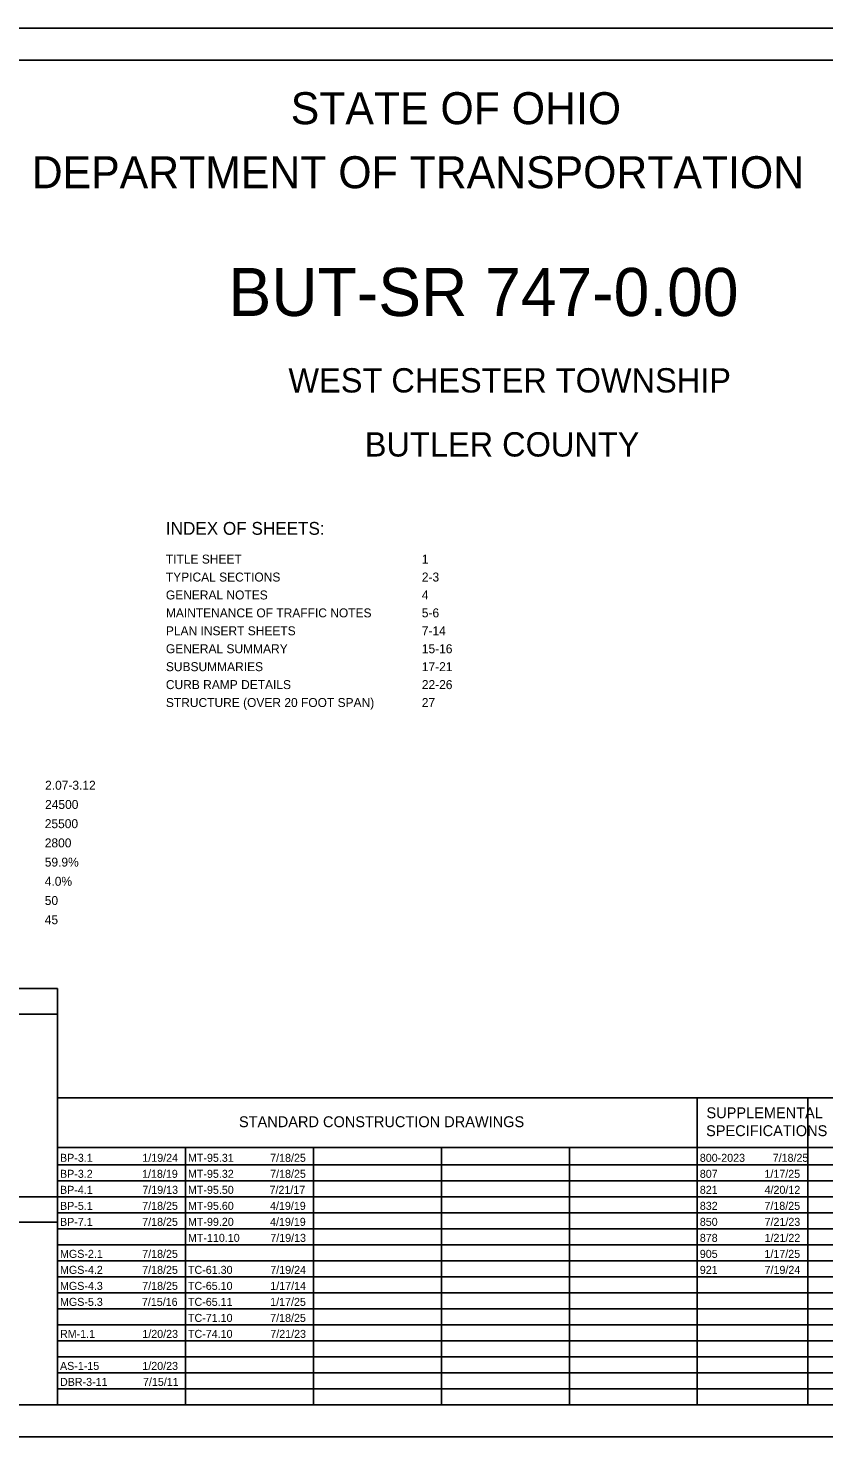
# Model space of a CAD drawing. Extents: x 0 to 34, y 0 to 22.
# Drawn here: x 9.69 to 22.13, y 0 to 22 of the extents above; entities that cross this region are included whole.
import ezdxf

# ---------------------------------------------------------------- set-up
doc = ezdxf.new("R2010")
doc.units = 0
for name, color, linetype in [('SH_Border', 7, 'Continuous'), ('SH_Cut_Line', 7, 'Continuous'), ('SH_Data', 7, 'Continuous'), ('SH_Text', 7, 'Continuous')]:
    doc.layers.add(name, color=color, linetype=linetype)

msp = doc.modelspace()

# ---------------------------------------------------------------- linework, layer by layer
at = {"layer": 'SH_Border'}
msp.add_lwpolyline([(1.5, 21.5), (33.5, 21.5), (33.5, 0.5), (1.5, 0.5)], close=True, dxfattribs=at)
at = {"layer": 'SH_Cut_Line'}
msp.add_lwpolyline([(0, 0), (34, 0), (34, 22), (0, 22)], close=True, dxfattribs=at)
at = {"layer": 'SH_Data'}
for p, q in [((7.35, 6.6), (10.15, 6.6)), ((10.15, 5.292), (23.6, 5.292)), ((10.15, 0.5), (10.15, 5.292)), ((20.15, 0.5), (20.15, 5.292)), ((21.875, 0.5), (21.875, 5.292)), ((10.15, 4.521), (23.6, 4.521)), ((12.15, 0.5), (12.15, 4.521)), ((14.15, 0.5), (14.15, 4.521)), ((16.15, 0.5), (16.15, 4.521)), ((18.15, 0.5), (18.15, 4.521)), ((10.15, 4.25), (23.6, 4.25)), ((10.15, 4), (23.6, 4)), ((10.15, 3.75), (23.6, 3.75)), ((7.35, 3.35), (10.15, 3.35)), ((10.15, 3.5), (23.6, 3.5)), ((10.15, 3.25), (23.6, 3.25)), ((10.15, 3), (23.6, 3)), ((10.15, 2.75), (23.6, 2.75)), ((10.15, 2.5), (23.6, 2.5)), ((10.15, 2.25), (23.6, 2.25)), ((10.15, 2), (23.6, 2)), ((10.15, 1.75), (23.6, 1.75)), ((10.15, 1.5), (23.6, 1.5)), ((10.15, 1.25), (23.6, 1.25)), ((10.15, 1), (23.6, 1)), ((10.15, 0.75), (23.6, 0.75))]:
    msp.add_line(p, q, dxfattribs=at)
for points in [[(10.15, 7), (7.35, 7), (7.35, 3.75), (10.15, 3.75)], [(10.15, 3.75), (7.35, 3.75), (7.35, 0.5), (10.15, 0.5)]]:
    msp.add_lwpolyline(points, close=True, dxfattribs=at)

# ---------------------------------------------------------------- texts
at = {"layer": 'SH_Text'}
for s, height, p in [('STATE OF OHIO', 0.5, (13.795, 20.5)), ('DEPARTMENT OF TRANSPORTATION', 0.5, (9.747, 19.5)), ('BUT-SR 747-0.00', 0.75, (12.823, 17.505)), ('WEST CHESTER TOWNSHIP', 0.38, (13.759, 16.31)), ('BUTLER COUNTY', 0.38, (14.953, 15.31)), ('INDEX OF SHEETS:', 0.2, (11.844, 14.088)), ('TITLE SHEET', 0.14, (11.844, 13.638)), ('1', 0.14, (15.844, 13.638)), ('TYPICAL SECTIONS', 0.14, (11.844, 13.358)), ('2-3', 0.14, (15.844, 13.358)), ('GENERAL NOTES', 0.14, (11.844, 13.078)), ('4', 0.14, (15.844, 13.078)), ('MAINTENANCE OF TRAFFIC NOTES', 0.14, (11.844, 12.798)), ('5-6', 0.14, (15.844, 12.798)), ('PLAN INSERT SHEETS', 0.14, (11.844, 12.518)), ('7-14', 0.14, (15.844, 12.518)), ('GENERAL SUMMARY', 0.14, (11.844, 12.238)), ('15-16', 0.14, (15.844, 12.238)), ('SUBSUMMARIES', 0.14, (11.844, 11.958)), ('17-21', 0.14, (15.844, 11.958)), ('CURB RAMP DETAILS', 0.14, (11.844, 11.678)), ('22-26', 0.14, (15.844, 11.678)), ('STRUCTURE (OVER 20 FOOT SPAN)', 0.14, (11.844, 11.398)), ('27', 0.14, (15.844, 11.398)), ('2.07-3.12', 0.14, (9.956, 10.106)), ('24500', 0.14, (9.956, 9.806)), ('25500', 0.14, (9.951, 9.506)), ('2800', 0.14, (9.951, 9.206)), ('59.9%', 0.14, (9.951, 8.906)), ('4.0%', 0.14, (9.951, 8.606)), ('50', 0.14, (9.951, 8.306)), ('45', 0.14, (9.951, 8.006)), ('SUPPLEMENTAL', 0.17, (20.293, 4.976)), ('STANDARD CONSTRUCTION DRAWINGS', 0.17, (12.986, 4.836)), ('SPECIFICATIONS', 0.17, (20.287, 4.696)), ('BP-3.1', 0.125, (10.189, 4.295)), ('1/19/24', 0.125, (11.476, 4.295)), ('MT-95.31', 0.125, (12.189, 4.295)), ('7/18/25', 0.125, (13.474, 4.295)), ('800-2023', 0.125, (20.189, 4.295)), ('7/18/25', 0.125, (21.328, 4.295)), ('BP-3.2', 0.125, (10.189, 4.045)), ('1/18/19', 0.125, (11.472, 4.045)), ('MT-95.32', 0.125, (12.189, 4.045)), ('7/18/25', 0.125, (13.474, 4.045)), ('807', 0.125, (20.189, 4.045)), ('1/17/25', 0.125, (21.199, 4.045)), ('BP-4.1', 0.125, (10.189, 3.795)), ('7/19/13', 0.125, (11.476, 3.795)), ('MT-95.50', 0.125, (12.189, 3.795)), ('7/21/17', 0.125, (13.464, 3.795)), ('821', 0.125, (20.189, 3.795)), ('4/20/12', 0.125, (21.201, 3.795)), ('BP-5.1', 0.125, (10.189, 3.545)), ('7/18/25', 0.125, (11.474, 3.545)), ('MT-95.60', 0.125, (12.189, 3.545)), ('4/19/19', 0.125, (13.472, 3.545)), ('832', 0.125, (20.189, 3.545)), ('7/18/25', 0.125, (21.199, 3.545)), ('BP-7.1', 0.125, (10.189, 3.295)), ('7/18/25', 0.125, (11.474, 3.295)), ('MT-99.20', 0.125, (12.189, 3.295)), ('4/19/19', 0.125, (13.472, 3.295)), ('850', 0.125, (20.189, 3.295)), ('7/21/23', 0.125, (21.201, 3.295)), ('MT-110.10', 0.125, (12.189, 3.045)), ('7/19/13', 0.125, (13.476, 3.045)), ('878', 0.125, (20.189, 3.045)), ('1/21/22', 0.125, (21.201, 3.045)), ('MGS-2.1', 0.125, (10.189, 2.795)), ('7/18/25', 0.125, (11.474, 2.795)), ('905', 0.125, (20.189, 2.795)), ('1/17/25', 0.125, (21.199, 2.795)), ('MGS-4.2', 0.125, (10.189, 2.545)), ('7/18/25', 0.125, (11.474, 2.545)), ('TC-61.30', 0.125, (12.189, 2.545)), ('7/19/24', 0.125, (13.476, 2.545)), ('921', 0.125, (20.189, 2.545)), ('7/19/24', 0.125, (21.201, 2.545)), ('MGS-4.3', 0.125, (10.189, 2.295)), ('7/18/25', 0.125, (11.474, 2.295)), ('TC-65.10', 0.125, (12.189, 2.295)), ('1/17/14', 0.125, (13.476, 2.295)), ('MGS-5.3', 0.125, (10.189, 2.045)), ('7/15/16', 0.125, (11.469, 2.045)), ('TC-65.11', 0.125, (12.189, 2.045)), ('1/17/25', 0.125, (13.474, 2.045)), ('TC-71.10', 0.125, (12.189, 1.795)), ('7/18/25', 0.125, (13.474, 1.795)), ('RM-1.1', 0.125, (10.189, 1.545)), ('1/20/23', 0.125, (11.476, 1.545)), ('TC-74.10', 0.125, (12.189, 1.545)), ('7/21/23', 0.125, (13.476, 1.545)), ('AS-1-15', 0.125, (10.189, 1.045)), ('1/20/23', 0.125, (11.476, 1.045)), ('DBR-3-11', 0.125, (10.189, 0.795)), ('7/15/11', 0.125, (11.486, 0.795))]:
    msp.add_text(s, height=height, dxfattribs=at).set_placement(p)

doc.saveas('drawing.dxf')
